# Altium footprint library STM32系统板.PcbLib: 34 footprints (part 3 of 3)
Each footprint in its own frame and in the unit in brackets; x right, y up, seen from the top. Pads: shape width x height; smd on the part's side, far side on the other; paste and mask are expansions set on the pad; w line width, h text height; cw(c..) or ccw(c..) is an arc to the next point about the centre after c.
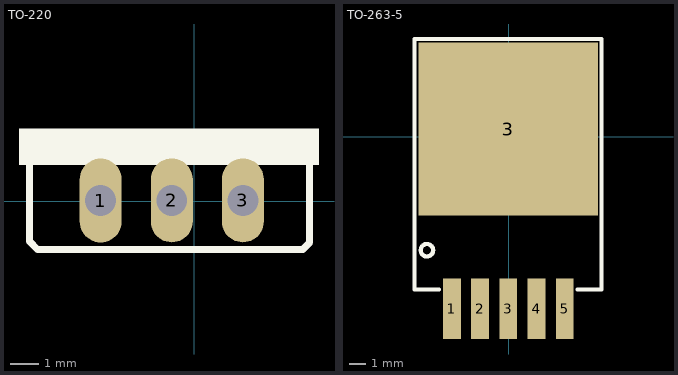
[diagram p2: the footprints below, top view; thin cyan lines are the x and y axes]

## TO-220 [mm]
pads (3):
  oval 1.5x3 hole 1.1: 1(-3.35,0.025) 2(-0.805,0.029) 3(1.735,0.029)
Top Overlay:
  region: 4.454,2.595 -6.267,2.595 -6.267,1.299 4.454,1.299
  lines w0.254: -5.885,1.574 -5.885,-1.442 -5.605,-1.723 3.872,-1.723 4.121,-1.474 4.121,1.352

## TO-263-5 [mm]
pads (6):
  rect 1.07x3.66 smd: 1(-3.425,-10.36) 2(-1.725,-10.36) 3(-0.025,-10.36) 4(1.675,-10.36) 5(3.375,-10.36)
  rect 10.8x10.41 smd: 3(-0.025,0.465)
Top Overlay:
  circle w0.254: c-4.931,-6.84 r0.376
  lines w0.254: -4.205,-9.21 -5.685,-9.21 -5.685,-6.39 -5.685,4.4 -5.685,5.89 5.595,5.89 5.595,4.4 5.595,-6.5 5.595,-9.19 5.585,-9.2 4.145,-9.2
